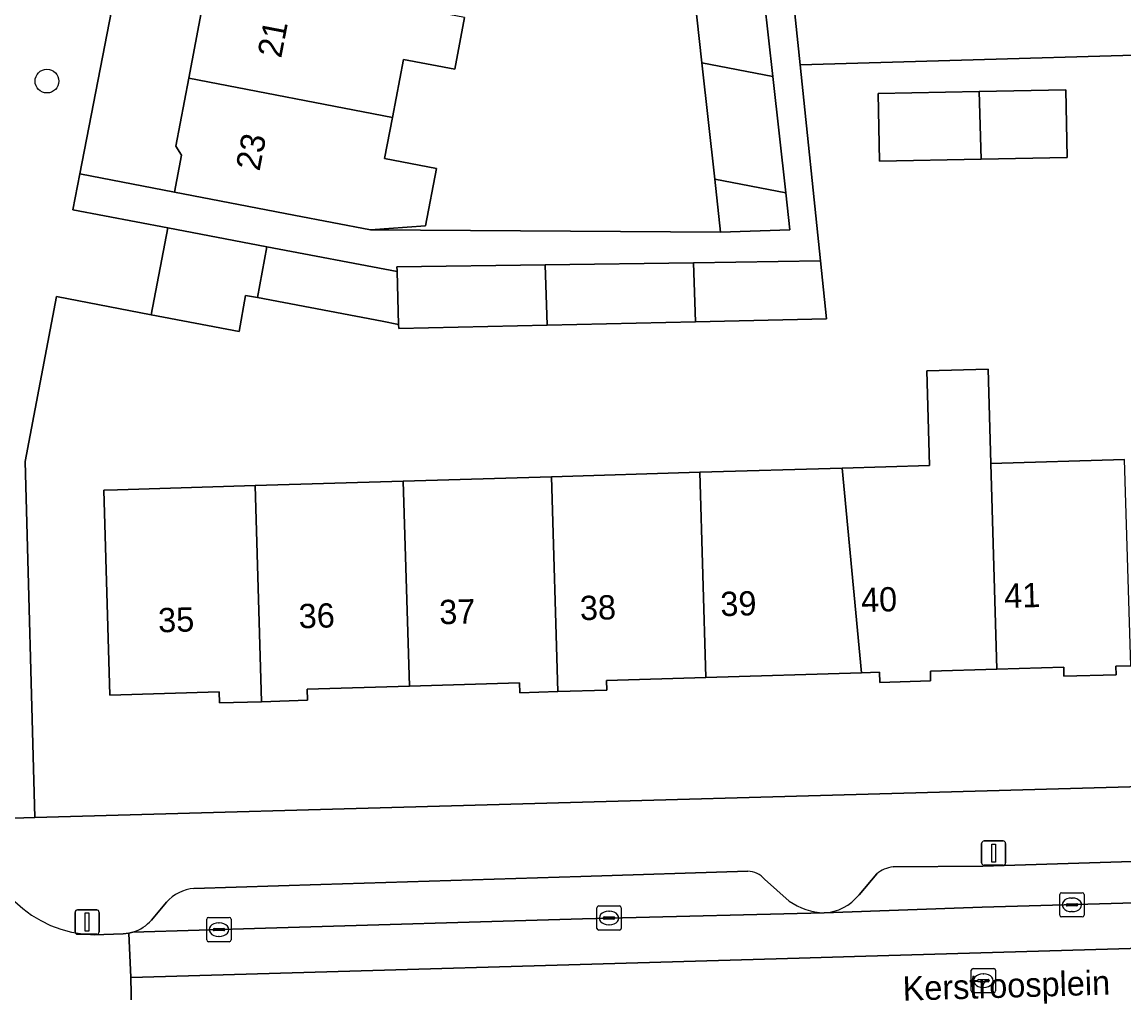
# Model space of a CAD drawing. Extents: x 162250 to 162661, y 380743 to 381606.
# Drawn here: x 162376.95 to 162422.34, y 381208.05 to 381248.05 of the extents above; entities that cross this region are included whole.
import ezdxf

# ---------------------------------------------------------------- set-up
doc = ezdxf.new("R2010")
doc.units = 0
for name, color, linetype in [('IMGEO_Boom', 7, 'Continuous'), ('IMGEO_Erf', 7, 'Continuous'), ('IMGEO_Kolk', 7, 'Continuous'), ('IMGEO_Lichtmast', 7, 'Continuous'), ('IMGEO_Openbare_ruimte_label', 7, 'Continuous'), ('IMGEO_Pand', 7, 'Continuous'), ('IMGEO_Pand_nummerreeks', 7, 'Continuous'), ('IMGEO_Parkeervlak_open', 7, 'Continuous'), ('IMGEO_Rijbaan_lokaal_gesloten', 7, 'Continuous'), ('IMGEO_Rioolput', 7, 'Continuous'), ('IMGEO_Voetpad_open', 7, 'Continuous'), ('IMGEO_Woonerf_open', 7, 'Continuous')]:
    doc.layers.add(name, color=color, linetype=linetype)

msp = doc.modelspace()

# ---------------------------------------------------------------- linework, layer by layer
at = {"layer": 'IMGEO_Boom'}
msp.add_circle((162377.973, 381245.613), 0.489, dxfattribs=at)
at = {"layer": 'IMGEO_Erf'}
for points in [[(162395.181, 381248.235), (162394.773, 381246.103), (162392.661, 381246.508), (162392.203, 381244.12), (162391.878, 381242.422), (162394.026, 381242.01), (162393.574, 381239.647), (162391.301, 381239.486), (162405.726, 381239.395), (162405.486, 381241.573), (162404.957, 381246.361), (162404.428, 381251.148)], [(162380.924, 381250), (162379.33, 381241.79), (162383.228, 381241.033), (162383.522, 381242.568), (162383.278, 381242.929), (162383.814, 381245.729), (162384.372, 381248.642)], [(162429.895, 381246.884), (162409, 381246.281), (162409.844, 381238.205), (162410.094, 381235.813), (162404.685, 381235.691), (162398.577, 381235.553), (162392.467, 381235.416), (162392.462, 381235.589), (162391.782, 381235.719), (162386.653, 381236.694), (162386.154, 381236.776), (162385.89, 381235.295), (162382.262, 381235.985), (162378.369, 381236.744), (162377.073, 381229.937), (162377.478, 381215.273), (162452.018, 381217.357)], [(162422.625, 381221.529), (162422.014, 381221.51), (162422.025, 381221.16), (162419.872, 381221.096), (162419.861, 381221.473), (162417.112, 381221.391), (162414.366, 381221.309), (162414.378, 381220.904), (162412.29, 381220.842), (162412.277, 381221.261), (162411.534, 381221.239), (162405.12, 381221.047), (162401.021, 381220.925), (162401.033, 381220.52), (162399.025, 381220.46), (162397.458, 381220.413), (162397.446, 381220.82), (162392.905, 381220.684), (162388.695, 381220.558), (162388.709, 381220.104), (162386.81, 381220.047), (162385.084, 381219.996), (162385.07, 381220.457), (162380.569, 381220.322), (162380.317, 381228.762), (162380.883, 381228.779), (162386.546, 381228.948), (162392.654, 381229.131), (162398.762, 381229.314), (162404.869, 381229.497), (162410.739, 381229.672), (162414.337, 381229.78), (162414.221, 381233.67), (162416.743, 381233.745), (162416.859, 381229.856), (162422.371, 381230.021)]]:
    msp.add_lwpolyline(points, dxfattribs=at)
msp.add_lwpolyline([(162412.268, 381242.314), (162412.212, 381245.096), (162416.379, 381245.181), (162419.953, 381245.253), (162420.009, 381242.471), (162416.462, 381242.399)], close=True, dxfattribs=at)
at = {"layer": 'IMGEO_Kolk'}
for p, q in [((162419.698, 381211.252), (162419.698, 381212.104)), ((162419.773, 381212.178), (162420.625, 381212.178)), ((162420.699, 381212.104), (162420.699, 381211.252)), ((162419.957, 381211.672), (162419.957, 381211.684)), ((162420, 381211.721), (162420.398, 381211.721)), ((162420.186, 381211.958), (162420.211, 381211.958)), ((162420.441, 381211.684), (162420.441, 381211.672)), ((162400.63, 381210.708), (162400.63, 381211.56)), ((162400.705, 381211.634), (162401.557, 381211.634)), ((162401.118, 381211.414), (162401.143, 381211.414)), ((162401.631, 381211.56), (162401.631, 381210.708)), ((162420.395, 381211.635), (162419.997, 381211.635)), ((162420.209, 381211.398), (162420.184, 381211.398)), ((162384.557, 381210.232), (162384.557, 381211.084)), ((162384.632, 381211.158), (162385.484, 381211.158)), ((162385.045, 381210.938), (162385.07, 381210.938)), ((162385.558, 381211.084), (162385.558, 381210.232)), ((162400.889, 381211.128), (162400.889, 381211.14)), ((162401.327, 381211.091), (162400.929, 381211.091)), ((162400.932, 381211.177), (162401.33, 381211.177)), ((162401.141, 381210.854), (162401.116, 381210.854)), ((162401.373, 381211.14), (162401.373, 381211.128)), ((162420.625, 381211.178), (162419.773, 381211.178)), ((162384.816, 381210.652), (162384.816, 381210.664)), ((162385.254, 381210.615), (162384.856, 381210.615)), ((162384.859, 381210.701), (162385.257, 381210.701)), ((162385.068, 381210.378), (162385.043, 381210.378)), ((162385.3, 381210.664), (162385.3, 381210.652)), ((162401.557, 381210.634), (162400.705, 381210.634)), ((162385.484, 381210.158), (162384.632, 381210.158))]:
    msp.add_line(p, q, dxfattribs=at)
for points in [[(162419.698, 381211.252), (162419.698, 381212.104)], [(162419.773, 381212.178), (162420.625, 381212.178)], [(162420.699, 381212.104), (162420.699, 381211.252)], [(162400.63, 381210.708), (162400.63, 381211.56)], [(162400.705, 381211.634), (162401.557, 381211.634)], [(162401.631, 381211.56), (162401.631, 381210.708)], [(162384.557, 381210.232), (162384.557, 381211.084)], [(162384.632, 381211.158), (162385.484, 381211.158)], [(162385.558, 381211.084), (162385.558, 381210.232)], [(162420.625, 381211.178), (162419.773, 381211.178)], [(162401.557, 381210.634), (162400.705, 381210.634)], [(162385.484, 381210.158), (162384.632, 381210.158)]]:
    msp.add_lwpolyline(points, dxfattribs=at)
for centre, radius, start, end in [((162419.775, 381212.102), 0.0765, 91.552, 178.448), ((162419.775, 381212.102), 0.0765, 91.552, 178.448), ((162420.623, 381212.102), 0.0765, 1.552, 88.448), ((162420.623, 381212.102), 0.0765, 1.552, 88.448), ((162419.997, 381211.681), 0.0403, 85.8775, 175.7526), ((162419.994, 381211.671), 0.0366, 178.938, 274.7102), ((162420.398, 381211.678), 0.043, 264.8664, 352.4533), ((162420.402, 381211.683), 0.0386, 1.7309, 96.639), ((162400.707, 381211.558), 0.0765, 91.552, 178.448), ((162400.707, 381211.558), 0.0765, 91.552, 178.448), ((162401.555, 381211.558), 0.0765, 1.552, 88.448), ((162401.555, 381211.558), 0.0765, 1.552, 88.448), ((162419.775, 381211.254), 0.0765, 181.552, 268.448), ((162419.775, 381211.254), 0.0765, 181.552, 268.448), ((162420.623, 381211.254), 0.0765, 271.552, 358.448), ((162420.623, 381211.254), 0.0765, 271.552, 358.448), ((162384.634, 381211.082), 0.0765, 91.552, 178.448), ((162384.634, 381211.082), 0.0765, 91.552, 178.448), ((162385.482, 381211.082), 0.0765, 1.552, 88.448), ((162385.482, 381211.082), 0.0765, 1.552, 88.448), ((162400.929, 381211.137), 0.0403, 85.8775, 175.7526), ((162400.926, 381211.127), 0.0366, 178.938, 274.7102), ((162401.33, 381211.134), 0.043, 264.8664, 352.4533), ((162401.334, 381211.139), 0.0386, 1.7309, 96.639), ((162384.856, 381210.661), 0.0403, 85.8775, 175.7526), ((162384.853, 381210.651), 0.0366, 178.938, 274.7102), ((162385.257, 381210.658), 0.043, 264.8664, 352.4533), ((162385.261, 381210.663), 0.0386, 1.7309, 96.639), ((162400.707, 381210.71), 0.0765, 181.552, 268.448), ((162400.707, 381210.71), 0.0765, 181.552, 268.448), ((162401.555, 381210.71), 0.0765, 271.552, 358.448), ((162401.555, 381210.71), 0.0765, 271.552, 358.448), ((162384.634, 381210.234), 0.0765, 181.552, 268.448), ((162384.634, 381210.234), 0.0765, 181.552, 268.448), ((162385.482, 381210.234), 0.0765, 271.552, 358.448), ((162385.482, 381210.234), 0.0765, 271.552, 358.448)]:
    msp.add_arc(centre, radius, start, end, dxfattribs=at)
for centre, major_axis, ratio, start_param, end_param in [((162420.185, 381211.678), (-0.387, 0.002), 0.722429, 4.712389, 7.853982), ((162420.21, 381211.678), (-0.39, 0.002), 0.717154, 1.570796, 4.712389), ((162401.117, 381211.134), (-0.387, 0.002), 0.722429, 4.712389, 7.853982), ((162401.142, 381211.134), (-0.39, 0.002), 0.717154, 1.570796, 4.712389), ((162385.044, 381210.658), (-0.387, 0.002), 0.722429, 4.712389, 7.853982), ((162385.069, 381210.658), (-0.39, 0.002), 0.717154, 1.570796, 4.712389)]:
    msp.add_ellipse(centre, major_axis=major_axis, ratio=ratio, start_param=start_param, end_param=end_param, dxfattribs=at)
at = {"layer": 'IMGEO_Lichtmast'}
for p, q in [((162416.479, 381213.408), (162416.479, 381214.208)), ((162416.479, 381214.208), (162416.479, 381213.408)), ((162416.579, 381214.308), (162417.369, 381214.308)), ((162417.369, 381214.308), (162416.579, 381214.308)), ((162417.469, 381214.208), (162417.469, 381213.408)), ((162417.469, 381213.408), (162417.469, 381214.208)), ((162417.369, 381213.308), (162416.579, 381213.308)), ((162416.579, 381213.308), (162417.369, 381213.308)), ((162379.131, 381210.568), (162379.131, 381211.368)), ((162379.131, 381211.368), (162379.131, 381210.568)), ((162379.231, 381211.468), (162380.021, 381211.468)), ((162380.021, 381211.468), (162379.231, 381211.468)), ((162380.121, 381211.368), (162380.121, 381210.568)), ((162380.121, 381210.568), (162380.121, 381211.368)), ((162380.021, 381210.468), (162379.231, 381210.468)), ((162379.231, 381210.468), (162380.021, 381210.468))]:
    msp.add_line(p, q, dxfattribs=at)
for points in [[(162416.899, 381214.183), (162417.049, 381214.183), (162417.049, 381213.433), (162416.899, 381213.433), (162416.899, 381214.183)], [(162379.551, 381211.343), (162379.701, 381211.343), (162379.701, 381210.593), (162379.551, 381210.593), (162379.551, 381211.343)]]:
    msp.add_lwpolyline(points, dxfattribs=at)
for centre, start, end in [((162416.579, 381214.208), 90, 180), ((162416.579, 381214.208), 90, 180), ((162417.369, 381214.208), 0, 90), ((162417.369, 381214.208), 360, 90), ((162416.579, 381213.408), 180, 270), ((162416.579, 381213.408), 180, 270), ((162417.369, 381213.408), 270, 0), ((162417.369, 381213.408), 270, 0), ((162379.231, 381211.368), 90, 180), ((162379.231, 381211.368), 90, 180), ((162380.021, 381211.368), 0, 90), ((162380.021, 381211.368), 360, 90), ((162379.231, 381210.568), 180, 270), ((162379.231, 381210.568), 180, 270), ((162380.021, 381210.568), 270, 0), ((162380.021, 381210.568), 270, 0)]:
    msp.add_arc(centre, 0.1, start, end, dxfattribs=at)
at = {"layer": 'IMGEO_Pand'}
for points in [[(162407.335, 381250.591), (162404.428, 381251.148), (162404.957, 381246.361), (162407.873, 381245.802)], [(162395.181, 381248.235), (162393.091, 381248.636), (162393.007, 381248.652), (162385.981, 381250), (162384.986, 381250.191), (162384.949, 381250), (162384.736, 381248.888), (162384.372, 381248.642), (162383.814, 381245.729), (162392.203, 381244.12), (162392.661, 381246.508), (162394.773, 381246.103)], [(162405.486, 381241.573), (162408.411, 381241.012), (162407.873, 381245.802), (162404.957, 381246.361)], [(162392.203, 381244.12), (162383.814, 381245.729), (162383.278, 381242.929), (162383.522, 381242.568), (162383.228, 381241.033), (162388.139, 381240.092), (162391.301, 381239.486), (162393.574, 381239.647), (162394.026, 381242.01), (162391.878, 381242.422)], [(162416.379, 381245.181), (162416.462, 381242.399), (162420.009, 381242.471), (162419.953, 381245.253)], [(162416.379, 381245.181), (162412.212, 381245.096), (162412.268, 381242.314), (162416.462, 381242.399)], [(162405.486, 381241.573), (162405.726, 381239.395), (162408.583, 381239.486), (162408.411, 381241.012)], [(162387.032, 381238.789), (162382.948, 381239.57), (162382.262, 381235.985), (162385.89, 381235.295), (162386.154, 381236.776), (162386.653, 381236.694)], [(162392.397, 381237.763), (162387.032, 381238.789), (162386.653, 381236.694), (162391.782, 381235.719), (162392.462, 381235.589)], [(162398.503, 381238.045), (162392.392, 381237.959), (162392.396, 381237.81), (162392.397, 381237.763), (162392.462, 381235.589), (162392.467, 381235.416), (162398.577, 381235.553)], [(162404.613, 381238.131), (162398.503, 381238.045), (162398.577, 381235.553), (162404.685, 381235.691)], [(162404.613, 381238.131), (162404.685, 381235.691), (162410.094, 381235.813), (162409.844, 381238.205)], [(162417.112, 381221.391), (162416.859, 381229.856), (162416.743, 381233.745), (162414.221, 381233.67), (162414.337, 381229.78), (162410.739, 381229.672), (162411.534, 381221.239), (162412.277, 381221.261), (162412.29, 381220.842), (162414.378, 381220.904), (162414.366, 381221.309)], [(162417.112, 381221.391), (162419.861, 381221.473), (162419.872, 381221.096), (162422.025, 381221.16), (162422.014, 381221.51), (162422.625, 381221.529), (162422.371, 381230.021), (162416.859, 381229.856)], [(162398.762, 381229.314), (162399.025, 381220.46), (162401.033, 381220.52), (162401.021, 381220.925), (162405.12, 381221.047), (162404.869, 381229.497)], [(162411.534, 381221.239), (162410.739, 381229.672), (162404.869, 381229.497), (162405.12, 381221.047)], [(162386.546, 381228.948), (162380.883, 381228.779), (162380.317, 381228.762), (162380.569, 381220.322), (162385.07, 381220.457), (162385.084, 381219.996), (162386.81, 381220.047)], [(162392.905, 381220.684), (162392.654, 381229.131), (162386.546, 381228.948), (162386.81, 381220.047), (162388.709, 381220.104), (162388.695, 381220.558)], [(162392.905, 381220.684), (162397.446, 381220.82), (162397.458, 381220.413), (162399.025, 381220.46), (162398.762, 381229.314), (162392.654, 381229.131)]]:
    msp.add_lwpolyline(points, close=True, dxfattribs=at)
at = {"layer": 'IMGEO_Parkeervlak_open'}
for points in [[(162446.377, 381214.198), (162416.534, 381213.265), (162412.829, 381213.238)], [(162406.848, 381213.062), (162399.973, 381212.851), (162389.255, 381212.518), (162384.028, 381212.357)], [(162408.552, 381211.829), (162407.538, 381212.733)], [(162409.993, 381211.345), (162416.495, 381211.579), (162442.593, 381212.327), (162453.821, 381212.653), (162453.82, 381212.683)], [(162412.156, 381212.954), (162411.428, 381212.093)], [(162382.899, 381211.789), (162382.282, 381211.052)], [(162381.517, 381210.554), (162386.979, 381210.713), (162400.034, 381211.098), (162401.131, 381211.133), (162409.993, 381211.345)]]:
    msp.add_lwpolyline(points, dxfattribs=at)
for centre, radius, start, end in [((162406.829, 381212.134), 0.929, 40.2011, 88.8142), ((162412.942, 381212.03), 1.213, 95.3631, 130.3956), ((162384.189, 381210.631), 1.733, 95.3233, 138.0906), ((162409.88, 381213.312), 1.971, 273.2891, 321.7729), ((162410.146, 381214.189), 2.848, 235.9569, 266.911), ((162380.984, 381212.209), 1.738, 287.8419, 318.2847)]:
    msp.add_arc(centre, radius, start, end, dxfattribs=at)
at = {"layer": 'IMGEO_Rijbaan_lokaal_gesloten'}
for points in [[(162453.821, 381212.653), (162442.593, 381212.327), (162416.495, 381211.579), (162409.993, 381211.345), (162401.131, 381211.133), (162400.034, 381211.098), (162386.979, 381210.713), (162381.517, 381210.554), (162381.351, 381210.51), (162381.43, 381208.683), (162408.962, 381209.481), (162411.235, 381209.547), (162453.857, 381210.783)], [(162453.911, 381207.983), (162453.857, 381210.783), (162411.235, 381209.547), (162408.962, 381209.481), (162381.43, 381208.683), (162381.477, 381205.975), (162409.05, 381206.74), (162411.31, 381206.802)]]:
    msp.add_lwpolyline(points, close=True, dxfattribs=at)
for points in [[(162381.43, 381208.683), (162381.351, 381210.51), (162381.114, 381210.477), (162379.916, 381210.447)], [(162379.35, 381204.095), (162381.488, 381204.167), (162381.515, 381204.168), (162381.579, 381204.167), (162381.577, 381204.213), (162381.477, 381205.975), (162381.43, 381208.683)]]:
    msp.add_lwpolyline(points, dxfattribs=at)
msp.add_arc((162380.015, 381215.273), 4.827, 182.5542, 268.8207, dxfattribs=at)
at = {"layer": 'IMGEO_Rioolput'}
for p, q in [((162416.051, 381208.129), (162416.051, 381208.981)), ((162416.126, 381209.055), (162416.978, 381209.055)), ((162417.052, 381208.981), (162417.052, 381208.129)), ((162416.31, 381208.549), (162416.31, 381208.561)), ((162416.748, 381208.512), (162416.35, 381208.512)), ((162416.353, 381208.598), (162416.751, 381208.598)), ((162416.539, 381208.835), (162416.564, 381208.835)), ((162416.794, 381208.561), (162416.794, 381208.549)), ((162416.978, 381208.055), (162416.126, 381208.055)), ((162416.562, 381208.275), (162416.537, 381208.275))]:
    msp.add_line(p, q, dxfattribs=at)
for points in [[(162416.051, 381208.129), (162416.051, 381208.981)], [(162416.126, 381209.055), (162416.978, 381209.055)], [(162417.052, 381208.981), (162417.052, 381208.129)], [(162416.978, 381208.055), (162416.126, 381208.055)]]:
    msp.add_lwpolyline(points, dxfattribs=at)
for centre, radius, start, end in [((162416.128, 381208.979), 0.0765, 91.552, 178.448), ((162416.128, 381208.979), 0.0765, 91.552, 178.448), ((162416.976, 381208.979), 0.0765, 1.552, 88.448), ((162416.976, 381208.979), 0.0765, 1.552, 88.448), ((162416.35, 381208.558), 0.0403, 85.8775, 175.7526), ((162416.347, 381208.548), 0.0366, 178.938, 274.7102), ((162416.751, 381208.555), 0.043, 264.8664, 352.4533), ((162416.755, 381208.56), 0.0386, 1.7309, 96.639), ((162416.128, 381208.131), 0.0765, 181.552, 268.448), ((162416.128, 381208.131), 0.0765, 181.552, 268.448), ((162416.976, 381208.131), 0.0765, 271.552, 358.448), ((162416.976, 381208.131), 0.0765, 271.552, 358.448)]:
    msp.add_arc(centre, radius, start, end, dxfattribs=at)
for centre, major_axis, ratio, start_param, end_param in [((162416.538, 381208.555), (-0.387, 0.002), 0.722429, 4.712389, 7.853982), ((162416.563, 381208.555), (-0.39, 0.002), 0.717154, 1.570796, 4.712389)]:
    msp.add_ellipse(centre, major_axis=major_axis, ratio=ratio, start_param=start_param, end_param=end_param, dxfattribs=at)
at = {"layer": 'IMGEO_Voetpad_open'}
for points in [[(162425.667, 381290.132), (162419.551, 381288.338), (162407.245, 381290.782), (162407.071, 381289.468), (162405.624, 381278.58), (162406.851, 381266.845), (162408.517, 381250.901), (162409, 381246.281), (162429.895, 381246.884)], [(162407.335, 381250.591), (162407.873, 381245.802), (162408.411, 381241.012), (162408.583, 381239.486), (162405.726, 381239.395), (162391.301, 381239.486), (162388.139, 381240.092), (162383.228, 381241.033), (162379.33, 381241.79), (162379.043, 381240.314), (162382.948, 381239.57), (162387.032, 381238.789), (162392.397, 381237.763), (162392.396, 381237.81), (162392.392, 381237.959), (162398.503, 381238.045), (162404.613, 381238.131), (162409.844, 381238.205), (162409, 381246.281), (162408.517, 381250.901)], [(162463.07, 381217.625), (162460.124, 381217.537), (162452.018, 381217.357), (162377.478, 381215.273), (162375.189, 381215.21), (162375.193, 381215.058)], [(162412.829, 381213.238), (162416.534, 381213.265), (162446.377, 381214.198), (162451.217, 381214.335)], [(162384.028, 381212.357), (162389.255, 381212.518), (162399.973, 381212.851), (162406.848, 381213.062)], [(162407.538, 381212.733), (162408.552, 381211.829)], [(162411.428, 381212.093), (162412.156, 381212.954)], [(162382.282, 381211.052), (162382.899, 381211.789)], [(162379.916, 381210.447), (162381.114, 381210.477), (162381.351, 381210.51), (162381.517, 381210.554)]]:
    msp.add_lwpolyline(points, dxfattribs=at)
for centre, radius, start, end in [((162380.015, 381215.273), 4.827, 182.5542, 268.8207), ((162406.829, 381212.134), 0.929, 40.2011, 88.8142), ((162412.942, 381212.03), 1.213, 95.3631, 130.3956), ((162384.189, 381210.631), 1.733, 95.3233, 138.0906), ((162409.88, 381213.312), 1.971, 273.2891, 321.7729), ((162410.146, 381214.189), 2.848, 235.9569, 266.911), ((162380.984, 381212.209), 1.738, 287.8419, 318.2847)]:
    msp.add_arc(centre, radius, start, end, dxfattribs=at)
at = {"layer": 'IMGEO_Woonerf_open'}
msp.add_lwpolyline([(162375.189, 381215.21), (162377.478, 381215.273), (162377.073, 381229.937), (162378.369, 381236.744), (162382.262, 381235.985), (162382.948, 381239.57), (162379.043, 381240.314), (162379.33, 381241.79), (162380.924, 381250), (162382.067, 381255.889), (162383.338, 381262.637), (162388.94, 381291.823), (162392.796, 381290.991), (162393.147, 381292.783), (162392.937, 381292.814), (162392.668, 381295.154), (162392.527, 381296.156), (162387.833, 381295.581), (162386.475, 381306.66), (162391.212, 381307.207), (162391.139, 381307.838), (162390.755, 381311.676), (162399.277, 381312.558), (162397.974, 381322.315)], dxfattribs=at)

# ---------------------------------------------------------------- texts
at = {"layer": 'IMGEO_Openbare_ruimte_label'}
msp.add_text('Kerstroosplein', height=1, rotation=1.7184, dxfattribs=at).set_placement((162413.24, 381207.727))
at = {"layer": 'IMGEO_Pand_nummerreeks'}
for s, rotation, p in [('21', 79.1598, (162387.62, 381246.529)), ('23', 79.158, (162386.728, 381241.875)), ('41', 1.6497, (162417.424, 381223.905)), ('38', 1.6497, (162399.942, 381223.401)), ('39', 1.6497, (162405.73, 381223.567)), ('40', 1.6497, (162411.524, 381223.734)), ('35', 1.6497, (162382.566, 381222.9)), ('36', 1.6497, (162388.357, 381223.067)), ('37', 1.6497, (162394.148, 381223.234))]:
    msp.add_text(s, height=1, rotation=rotation, dxfattribs=at).set_placement(p)

doc.saveas('drawing.dxf')
